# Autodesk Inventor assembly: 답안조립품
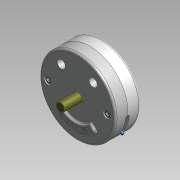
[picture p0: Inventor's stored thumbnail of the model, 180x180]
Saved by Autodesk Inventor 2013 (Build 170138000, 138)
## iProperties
Created: 2015-04
Part Number: 답안조립품
Document SubType Name: 조립품
Designer: Administrator
Author: Administrator
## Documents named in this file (10)
- C:\Users\Administrator\Desktop\450406V1002\답안조립품.iam
- C:\Users\Administrator\Desktop\450406V1002\본체.ipt
- C:\Users\Administrator\Desktop\450406V1002\M 10 x 35.ipt
- C:\Users\Administrator\Desktop\450406V1002\덮개.ipt
- C:\Users\Administrator\Desktop\450406V1002\멈춤링.ipt
- C:\Users\Administrator\Desktop\450406V1002\베어링62_22.ipt
- C:\Users\Administrator\Desktop\450406V1002\슬라이더.ipt
- C:\Users\Administrator\Desktop\450406V1002\슬라이더2.ipt
- C:\Users\Administrator\Desktop\450406V1002\축.ipt
- C:\Users\Administrator\Desktop\450406V1002\평행핀.ipt
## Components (2 placed, 1 different names)
1. M 10 x 35:1
2. M 10 x 35:2
